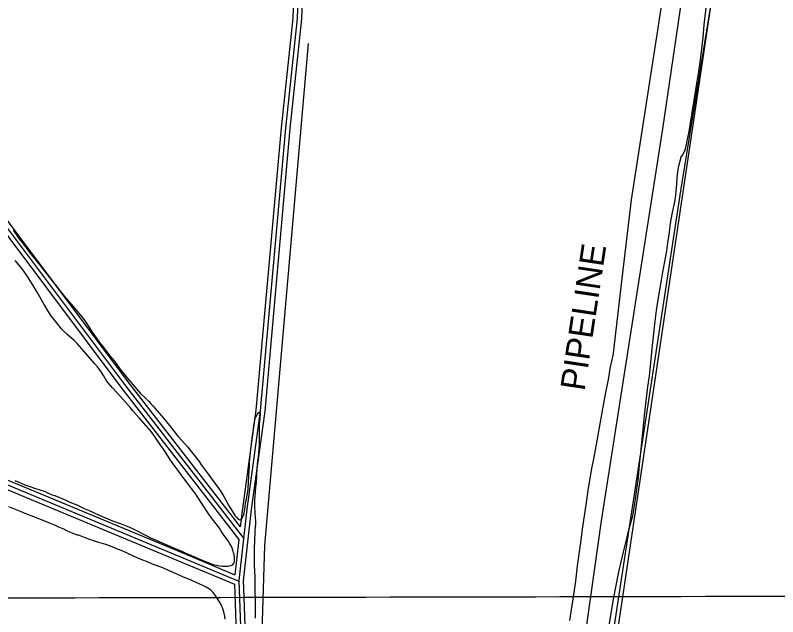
# Model space of a CAD drawing. Extents: x 3355724 to 3393621, y 594744 to 620174.
# Drawn here: x 3361195 to 3363783, y 606129 to 608168 of the extents above; entities that cross this region are included whole.
import ezdxf

# ---------------------------------------------------------------- set-up
doc = ezdxf.new("R2010")
doc.units = 0
for name, color, linetype in [('V-GRID-MAJR', 7, 'Continuous'), ('V-ROAD-CNTR', 7, 'Continuous'), ('V-SITE-VEGE', 7, 'Continuous'), ('V-TOPO-BNDY', 7, 'Continuous'), ('V-TOPO-SHOR', 7, 'Continuous'), ('V-UTIL-IDEN', 7, 'Continuous'), ('V-UTIL-LINE', 7, 'Continuous')]:
    doc.layers.add(name, color=color, linetype=linetype)

msp = doc.modelspace()

# ---------------------------------------------------------------- linework, layer by layer
at = {"layer": 'V-GRID-MAJR'}
msp.add_spline([(3359834, 606189.7), (3365100.7, 606201.5), (3370367.4, 606214.2), (3375634.1, 606227.6), (3380900.8, 606241.7), (3386167.5, 606256.7), (3391434.2, 606272.4)], degree=3, dxfattribs=at)
at = {"layer": 'V-ROAD-CNTR'}
for points in [[(3362168.2, 609045.4), (3362172.2, 609024), (3362169, 609012.5), (3362166.7, 608992.5), (3362171.4, 608969.4), (3362159, 609053.6), (3362178.6, 608925.1), (3362151.8, 608157.3), (3362112.4, 607785.3), (3362026.8, 606827.1), (3361980.8, 606493.8), (3361953.6, 606251.2), (3361963.6, 605972.8), (3361960.2, 605745.2), (3361949, 605614.3), (3361883.7, 605181.8), (3361826.7, 604780.1), (3361761.1, 604140.5), (3361706.5, 603460.6)], [(3362148.1, 609025.5), (3362163.5, 608924.3), (3362136.8, 608158.4), (3362097.5, 607786.7), (3362011.9, 606828.8), (3361965.9, 606495.7), (3361958.9, 606433.1)], [(3362176.7, 609037.3), (3362193.6, 608926), (3362166.7, 608156.3), (3362127.4, 607783.8), (3362041.7, 606825.4), (3361995.7, 606492), (3361968.6, 606250.6), (3361969.5, 606224.4)], [(3360846.6, 607833.9), (3361047.8, 607581), (3361553.7, 606907), (3361954.1, 606390.3)], [(3360858.3, 607843.2), (3361059.6, 607590.2), (3361565.6, 606916.1), (3361969.7, 606394.6)], [(3360870, 607852.6), (3361071.5, 607599.3), (3361577.5, 606925.2), (3361958.9, 606433.1)], [(3360475.4, 606717), (3360812.3, 606732.5), (3360826.8, 606731.2), (3360841.5, 606726.2), (3360872.9, 606715), (3361758.3, 606347)], [(3359830.5, 606689), (3360285.4, 606693.2), (3360812, 606717.5), (3360823.7, 606716.5), (3360836.6, 606712), (3360867.5, 606701), (3361953.4, 606249.7)], [(3360865.2, 606685.7), (3361911.8, 606250.7)], [(3361954.1, 606390.3), (3361940.7, 606271.2)], [(3361758.3, 606347), (3361940.7, 606271.2)], [(3361939, 606239.4), (3361948.6, 605972.6), (3361945.2, 605746), (3361934.1, 605616), (3361868.8, 605184), (3361811.8, 604781.9), (3361746.1, 604141.9), (3361691.5, 603462), (3361623, 602797.1), (3361550, 602043.9), (3361443.2, 600948.1), (3361375.8, 600412.9), (3361354.8, 600183.8), (3361345.9, 600163.2), (3361343.8, 600157.9)], [(3361911.8, 606250.7), (3361939, 606239.4)], [(3361969.5, 606224.4), (3361978.6, 605972.9), (3361975.2, 605744.4), (3361963.9, 605612.5), (3361898.5, 605179.6), (3361841.6, 604778.3), (3361776, 604139.2), (3361721.4, 603459.3), (3361652.9, 602794.1), (3361579.8, 602041), (3361473, 600944.8), (3361406.2, 600414)]]:
    msp.add_lwpolyline(points, dxfattribs=at)
at = {"layer": 'V-SITE-VEGE'}
for p, q in [((3363533.1, 608136.3), (3363540.7, 608202.8)), ((3363529.3, 608093.1), (3363533.1, 608136.3)), ((3363521.7, 608026.7), (3363529.3, 608093.1)), ((3363515.7, 607984.3), (3363521.7, 608026.7)), ((3363509.1, 607943.5), (3363515.7, 607984.3)), ((3363499.7, 607886.6), (3363509.1, 607943.5)), ((3363494.7, 607852.3), (3363499.7, 607886.6)), ((3363486.3, 607802.7), (3363494.7, 607852.3)), ((3363481.6, 607774.3), (3363486.3, 607802.7)), ((3363474.6, 607743), (3363481.6, 607774.3)), ((3363469.9, 607715.3), (3363473.3, 607729.8)), ((3363473.3, 607729.8), (3363474.6, 607743)), ((3363458.8, 607693.7), (3363466.7, 607708)), ((3363466.7, 607708), (3363469.9, 607715.3)), ((3363448.1, 607662.5), (3363453.2, 607682.1)), ((3363453.2, 607682.1), (3363454.1, 607685.8)), ((3363454.1, 607685.8), (3363458.8, 607693.7)), ((3363444.5, 607645), (3363448.1, 607662.5)), ((3363441.3, 607617.3), (3363444.5, 607645)), ((3363440.5, 607595.3), (3363441.3, 607617.3)), ((3363436.2, 607558), (3363440.5, 607595.3)), ((3363433.2, 607535.4), (3363436.2, 607558)), ((3363425.9, 607499), (3363433.2, 607535.4)), ((3363420.7, 607475.7), (3363425.9, 607499)), ((3363417.7, 607453.8), (3363420.7, 607475.7)), ((3363415.4, 607431.8), (3363417.7, 607453.8)), ((3363409.7, 607396.8), (3363415.4, 607431.8)), ((3363405.7, 607369.1), (3363409.7, 607396.8)), ((3363392.1, 607297), (3363405.7, 607369.1)), ((3363384.5, 607249.5), (3363392.1, 607297)), ((3363378.9, 607217.5), (3363384.5, 607249.5)), ((3363371.1, 607167.1), (3363378.9, 607217.5)), ((3363366.9, 607131.3), (3363371.1, 607167.1)), ((3363356.1, 607037.8), (3363366.9, 607131.3)), ((3363352.5, 607000.5), (3363356.1, 607037.8)), ((3363347.6, 606945.7), (3363352.5, 607000.5)), ((3363341.8, 606908.5), (3363347.6, 606945.7)), ((3363334.5, 606850.8), (3363341.8, 606908.5)), ((3363330.9, 606810.5), (3363334.5, 606850.8)), ((3363319.7, 606707.5), (3363330.9, 606810.5)), ((3363313.7, 606643.2), (3363319.7, 606707.5)), ((3363309.9, 606600.7), (3363313.7, 606643.2)), ((3363304.8, 606560.6), (3363309.9, 606600.7)), ((3363296.8, 606505.1), (3363304.8, 606560.6)), ((3363290.4, 606470.8), (3363296.8, 606505.1)), ((3363277, 606423.7), (3363290.4, 606470.8)), ((3363270, 606393.8), (3363277, 606423.7)), ((3363262.2, 606362.6), (3363270, 606393.8)), ((3363251.7, 606315.3), (3363262.2, 606362.6)), ((3363243.1, 606280.4), (3363251.7, 606315.3)), ((3363225, 606188.6), (3363243.1, 606280.4)), ((3363215.6, 606133.2), (3363225, 606188.6)), ((3363209.8, 606093.7), (3363215.6, 606133.2))]:
    msp.add_line(p, q, dxfattribs=at)
for points in [[(3363077.1, 606116.3), (3363089.6, 606196.5), (3363097.4, 606249), (3363103, 606301.7), (3363114, 606380.5), (3363121.1, 606433.8), (3363131.9, 606508.2), (3363138.8, 606557.2), (3363150.1, 606625.7), (3363159.1, 606670.1), (3363171.9, 606737.9), (3363179.4, 606782.4), (3363191.3, 606845.8), (3363198.5, 606883.7), (3363209.4, 606938.3), (3363214.2, 606970.4), (3363224.8, 607019.9), (3363225.7, 607022.8), (3363254.1, 607275.6), (3363286.7, 607542.2), (3363375.4, 608117.9), (3363414.1, 608371.1)], [(3361188.5, 607439.6), (3361199.2, 607423.6), (3361206.7, 607412.1), (3361219.4, 607396), (3361241.2, 607367.6), (3361250.2, 607356.1), (3361274.3, 607326.2), (3361298.8, 607294.7), (3361319.1, 607269.2), (3361335.1, 607249.7), (3361345.9, 607236.1), (3361362.7, 607215.1), (3361392.2, 607180.4), (3361404.6, 607166.3), (3361421.4, 607145.3), (3361432, 607130.5), (3361447.1, 607108.2), (3361456.8, 607093.6), (3361471.3, 607072.7), (3361481.4, 607059.1), (3361491.9, 607045.9), (3361516.7, 607013.7), (3361531.9, 606995.4), (3361550.7, 606969.7), (3361564.8, 606951.2), (3361574.4, 606939.5), (3361587.6, 606923.9), (3361595.7, 606914.5), (3361605.5, 606902.2), (3361618.9, 606886.4), (3361636.1, 606870.9), (3361641.2, 606865.9), (3361646.1, 606861.2), (3361648.9, 606859.6), (3361652.9, 606854.5), (3361662.4, 606843.9), (3361669.7, 606835.3), (3361698.5, 606802.1), (3361719, 606777.5), (3361739, 606751.4), (3361747.4, 606741.2), (3361760.8, 606725.8), (3361769.7, 606715.6), (3361780.1, 606704.3), (3361788.9, 606693.6), (3361802.1, 606676.8), (3361810.1, 606665.9), (3361818.8, 606654.5), (3361827.8, 606642.1), (3361841.4, 606624.3), (3361872.6, 606581.4), (3361885.4, 606564.4), (3361893, 606553.5), (3361903.6, 606536), (3361909.6, 606524), (3361918.6, 606507.5), (3361924.6, 606498), (3361932.9, 606485.4), (3361941.7, 606471.3), (3361945.8, 606465.7), (3361951.8, 606459.5), (3361955.7, 606457.4), (3361962.1, 606458.6), (3361965.7, 606462.6), (3361969.5, 606471.9), (3361971.5, 606480), (3361975.1, 606501.4), (3361977.1, 606514.6), (3361978.7, 606523.1), (3361982.9, 606546.4), (3361985.1, 606561), (3361985.5, 606566.5), (3361986.9, 606581.8), (3361987.9, 606609.3), (3361988.5, 606621.4), (3361989.7, 606640.1), (3361990.6, 606653.3), (3361993.7, 606686), (3361995.9, 606704.7), (3361998.9, 606733.9), (3362003.2, 606764.9), (3362005.4, 606779), (3362006.9, 606787.9), (3362009.3, 606800.4), (3362012.4, 606807.6), (3362017.9, 606816.5), (3362020.8, 606820.4), (3362025.3, 606823.2), (3362026.7, 606818), (3362025.2, 606799.9), (3362024.3, 606792.1), (3362023, 606780.6), (3362022.4, 606763.7), (3362022.7, 606723.4), (3362022.5, 606712.1), (3362021.9, 606695.7), (3362021, 606685), (3362019.1, 606668.7), (3362017.7, 606657.9), (3362015.3, 606629.7), (3362014.2, 606613), (3362013.8, 606601.7), (3362013.2, 606591.6), (3362012.4, 606581.7), (3362010.9, 606567.9), (3362008.1, 606537.8), (3362007.5, 606525.6), (3362007.2, 606517.6), (3362007.3, 606498.2), (3362007.8, 606488.3), (3362008.2, 606482.3), (3362008.5, 606476.1), (3362009, 606467.8), (3362009.6, 606462.7), (3362010, 606455.9), (3362010.4, 606451.9), (3362010.9, 606448), (3362010.7, 606442.6), (3362010.4, 606438.8), (3362009.5, 606436.2), (3362008.8, 606418.3), (3362008.2, 606406.7), (3362007.6, 606398.6), (3362007, 606385.9), (3362006.7, 606377.3), (3362006.5, 606369.2), (3362006, 606355.7), (3362006, 606345.6), (3362005.6, 606330.2), (3362005.7, 606320.1), (3362006.3, 606303.7), (3362007.6, 606281.6), (3362008.3, 606264.7), (3362008.5, 606225.1), (3362008.8, 606206.5), (3362009.1, 606193.2), (3362009, 606145), (3362009.3, 606124.1)], [(3361194, 606591), (3361207.7, 606584.9), (3361227.9, 606576.2), (3361241.8, 606571), (3361263.6, 606563.4), (3361278.5, 606558.7), (3361293.7, 606554.2), (3361296.4, 606553.3), (3361304.3, 606549.3), (3361307.9, 606547.9), (3361320.5, 606542.4), (3361329.7, 606539.3), (3361366.6, 606524.2), (3361376.5, 606519.3), (3361391.5, 606513.1), (3361402.1, 606508.9), (3361418.4, 606501.5), (3361429.6, 606496), (3361446.6, 606488.4), (3361479.7, 606472.9), (3361525.2, 606453.9), (3361554.8, 606443.2), (3361566.3, 606438.9), (3361583.4, 606431.8), (3361595, 606426.4), (3361642.3, 606402.5), (3361654.5, 606396.4), (3361673.4, 606387.9), (3361685.5, 606382.3), (3361730.2, 606363.1), (3361762.4, 606350), (3361774.3, 606344.6), (3361793, 606336.6), (3361824.2, 606323), (3361855.2, 606310.3), (3361867.3, 606306), (3361883.6, 606301.9), (3361888, 606301.1), (3361899.9, 606299.8), (3361906.7, 606299.6), (3361916.1, 606300.4), (3361922.5, 606301.2), (3361930, 606303.9), (3361934.1, 606306.2), (3361938.1, 606311.3), (3361939.1, 606316), (3361939.4, 606324.2), (3361939.3, 606330), (3361937.6, 606339.5), (3361936, 606345.7), (3361933.6, 606354.6), (3361931.1, 606360.8), (3361928.6, 606367.2), (3361922.6, 606377.7), (3361917.6, 606385.5), (3361902.8, 606405.3), (3361894.5, 606418.2), (3361888.2, 606428.5), (3361876.9, 606443.9), (3361867.8, 606455.3), (3361854.9, 606473.4), (3361826, 606515.9), (3361807.5, 606544.7), (3361792.9, 606563.3), (3361782.8, 606576.9), (3361776.2, 606586.5), (3361765.5, 606601.1), (3361758.5, 606610), (3361747.6, 606624.5), (3361740, 606634.4), (3361728.2, 606651.4), (3361720.2, 606663.4), (3361707.8, 606683), (3361698.7, 606696.4), (3361688.8, 606709.8), (3361674.8, 606730.6), (3361665.5, 606744), (3361656, 606756.3), (3361640.8, 606774.3), (3361615.3, 606803.2), (3361593, 606827.7), (3361587, 606835.4), (3361560.5, 606866.1), (3361524.3, 606906.2), (3361505.2, 606928.3), (3361500.4, 606936.9), (3361494.5, 606946.4), (3361486.3, 606958.6), (3361473.9, 606976), (3361465.3, 606986.2), (3361443.2, 607012.2), (3361428.9, 607028.5), (3361405, 607054.9), (3361395.3, 607064.9), (3361370.1, 607087.2), (3361360.8, 607096.2), (3361352.2, 607105.1), (3361339.5, 607120.5), (3361330.3, 607131.9), (3361315.9, 607150.5), (3361306.8, 607164.4), (3361293.2, 607187.3), (3361269.4, 607229.5), (3361259.7, 607245.9), (3361244.9, 607270.1), (3361234.8, 607285.3), (3361218.4, 607307.9), (3361195, 607337)], [(3361907.4, 606120.6), (3361906.2, 606130.6), (3361903.3, 606145.6), (3361898.2, 606159.2), (3361896.5, 606163.2), (3361890.3, 606175.4), (3361879.5, 606192.7), (3361875.6, 606198.6), (3361866.6, 606211.2), (3361860.1, 606217.8), (3361854.6, 606222), (3361842.9, 606228.7), (3361833.6, 606233.2), (3361809.5, 606245.2), (3361794.5, 606251.5), (3361790, 606253.7), (3361765.9, 606263.2), (3361751.3, 606269.3), (3361741, 606274.4), (3361713.6, 606286.6), (3361695.8, 606294.1), (3361683.2, 606299), (3361661.5, 606307.3), (3361646.3, 606313.3), (3361622.8, 606322.3), (3361608.6, 606328.6), (3361593.8, 606335.6), (3361557.6, 606351.7), (3361542.6, 606358.1), (3361518.2, 606367.6), (3361502.5, 606373.2), (3361478.4, 606380.8), (3361461.2, 606386.4), (3361435.4, 606395.5), (3361418.9, 606401.6), (3361409.9, 606404.7), (3361406.9, 606405.5), (3361397.6, 606408.8), (3361380.8, 606415.4), (3361370, 606420.3), (3361359.8, 606425.3), (3361343.6, 606432.4), (3361332.4, 606437.6), (3361314.9, 606444.7), (3361283.9, 606457.1), (3361271.5, 606462.2), (3361252.2, 606469.6), (3361240.2, 606474), (3361223.2, 606480.7), (3361212.6, 606485.3), (3361196.3, 606492.5), (3361173.6, 606500.8)]]:
    msp.add_lwpolyline(points, dxfattribs=at)
at = {"layer": 'V-TOPO-BNDY'}
msp.add_line((3364077.7, 611719.6), (3362934.4, 604035.2), dxfattribs=at)
at = {"layer": 'V-TOPO-SHOR'}
for points in [[(3363791.6, 610246.1), (3363616.7, 608931), (3363656.9, 608835.3), (3363452.4, 607572.4), (3363130.4, 605462.4), (3363059.5, 605078.7), (3362950.4, 604015.8), (3361905.9, 603230.1), (3361812, 602470.9), (3361688.7, 600736.9)], [(3362188.8, 608072.4), (3362041.5, 606370.3), (3362019.3, 605675.2), (3361956.4, 605307.5), (3361869.9, 604756), (3361839.3, 604252.6), (3361769.2, 603541.3), (3361691.4, 602758.2), (3361458.2, 600272.9), (3361442.6, 600145)]]:
    msp.add_lwpolyline(points, dxfattribs=at)
at = {"layer": 'V-UTIL-LINE'}
msp.add_lwpolyline([(3363981.6, 611801.4), (3363391.3, 607783.2), (3363183.4, 606453.7), (3363012, 605234.8), (3362873.9, 604089.7), (3361819.2, 603277.1), (3361633.7, 601361.7), (3361598.4, 600688.7), (3361528, 600151.1)], dxfattribs=at)

# ---------------------------------------------------------------- texts
at = {"layer": 'V-UTIL-IDEN'}
msp.add_text('PIPELINE', height=83, rotation=81.4461, dxfattribs=at).set_placement((3363126.6, 606891.9))

doc.saveas('drawing.dxf')
